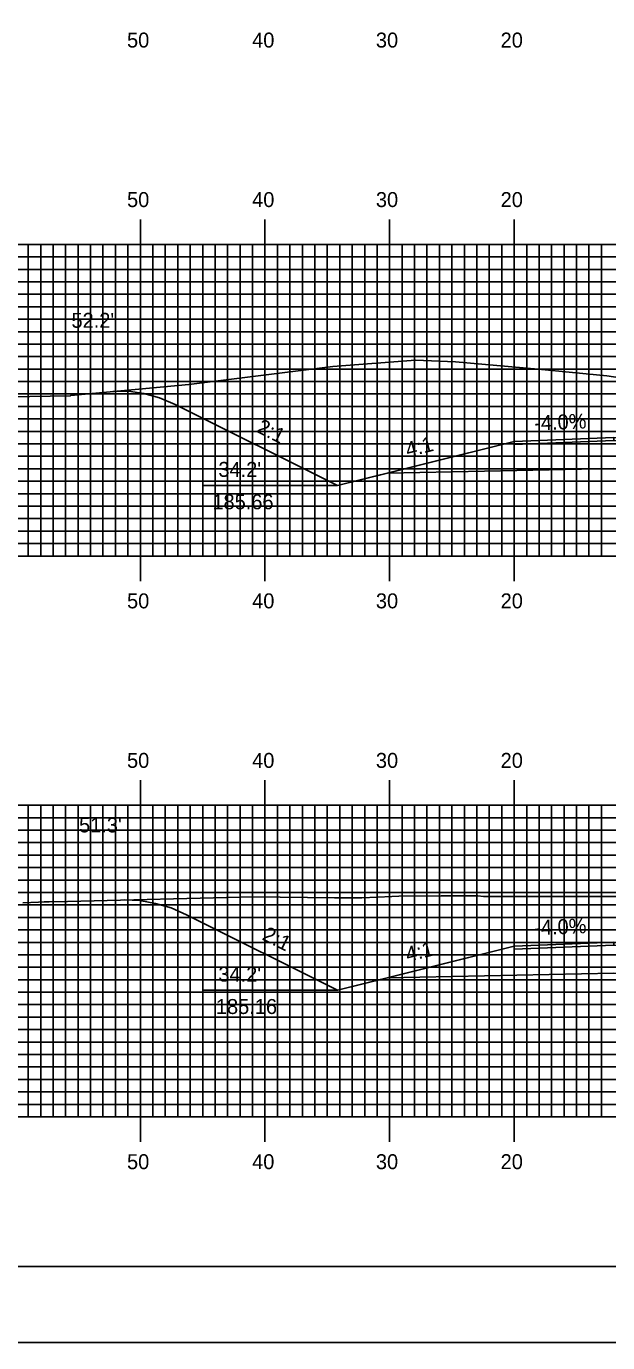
# Model space of a CAD drawing. Extents: x 1798388 to 1798731, y 442591 to 442811.
# Drawn here: x 1798494.3 to 1798541, y 442590.5 to 442696.2 of the extents above; entities that cross this region are included whole.
import ezdxf

# ---------------------------------------------------------------- set-up
doc = ezdxf.new("R2010")
doc.units = 0
for name, color, linetype in [('ANNOTATION', 7, 'Continuous'), ('BORDER', 7, 'Continuous'), ('D_Roadway_Centerline', 7, 'Continuous'), ('D_Roadway_Edge_Shoulder', 7, 'Continuous'), ('D_Roadway_SlopeLines', 7, 'Continuous'), ('D_Roadway_SubGrade', 7, 'Continuous'), ('D_Text_Standard', 7, 'Continuous'), ('H_V ANNOTATION', 7, 'Continuous'), ('MAJOR', 7, 'Continuous'), ('MINOR', 7, 'Continuous'), ('PDRAIN', 7, 'Continuous'), ('PLOT BOUNDARY', 7, 'Continuous'), ('S_Roadway_Centerline', 7, 'Continuous')]:
    doc.layers.add(name, color=color, linetype=linetype)

msp = doc.modelspace()

# ---------------------------------------------------------------- linework, layer by layer
at = {"layer": 'BORDER'}
msp.add_lwpolyline([(1798403.87, 442596.67), (1798723.87, 442596.67), (1798723.87, 442806.67), (1798403.87, 442806.67)], close=True, dxfattribs=at)
at = {"layer": 'D_Roadway_Centerline'}
for points in [[(1798501.26, 442666.86), (1798502.51, 442666.89), (1798503.76, 442666.72), (1798505.01, 442666.37), (1798506.26, 442665.84), (1798519.3, 442659.33), (1798523.3, 442660.33), (1798533.47, 442662.87), (1798541.47, 442663.19), (1798553.47, 442662.95), (1798565.47, 442662.71), (1798573.47, 442662.39), (1798583.64, 442659.85), (1798587.64, 442658.85), (1798594.53, 442662.29), (1798595.78, 442662.83), (1798597.03, 442663.19), (1798598.28, 442663.39), (1798599.53, 442663.41)], [(1798502.18, 442626.07), (1798503.43, 442626.02), (1798504.68, 442625.8), (1798505.93, 442625.43), (1798507.18, 442624.88), (1798519.3, 442618.83), (1798523.3, 442619.83), (1798533.47, 442622.37), (1798541.47, 442622.69), (1798553.47, 442622.45), (1798565.47, 442622.21), (1798573.47, 442621.89), (1798583.64, 442619.35), (1798587.64, 442618.35), (1798593.98, 442621.51), (1798595.23, 442622.06), (1798596.48, 442622.45), (1798597.73, 442622.68), (1798598.98, 442622.75)]]:
    msp.add_lwpolyline(points, dxfattribs=at)
at = {"layer": 'D_Roadway_Edge_Shoulder'}
for points in [[(1798541.47, 442663.19), (1798533.47, 442662.87), (1798533.47, 442662.62), (1798541.47, 442662.94)], [(1798541.47, 442622.69), (1798533.47, 442622.37), (1798533.47, 442622.12), (1798541.47, 442622.44)]]:
    msp.add_lwpolyline(points, close=True, dxfattribs=at)
at = {"layer": 'D_Roadway_SlopeLines'}
for points in [[(1798519.3, 442659.33), (1798506.26, 442665.84), (1798505.01, 442666.37), (1798503.76, 442666.72), (1798502.51, 442666.89), (1798501.26, 442666.86)], [(1798533.47, 442662.87), (1798519.3, 442659.33)], [(1798519.3, 442618.83), (1798507.18, 442624.88), (1798505.93, 442625.43), (1798504.68, 442625.8), (1798503.43, 442626.02), (1798502.18, 442626.07)], [(1798533.47, 442622.37), (1798519.3, 442618.83)]]:
    msp.add_lwpolyline(points, dxfattribs=at)
at = {"layer": 'D_Roadway_SubGrade'}
for points in [[(1798541.47, 442660.69), (1798523.3, 442660.33), (1798533.47, 442662.87), (1798533.47, 442662.62), (1798541.47, 442662.94), (1798553.47, 442662.7), (1798565.47, 442662.46), (1798573.47, 442662.14), (1798573.47, 442662.39), (1798583.64, 442659.85), (1798565.47, 442660.21), (1798553.47, 442660.45)], [(1798541.47, 442620.19), (1798523.3, 442619.83), (1798533.47, 442622.37), (1798533.47, 442622.12), (1798541.47, 442622.44), (1798553.47, 442622.2), (1798565.47, 442621.96), (1798573.47, 442621.64), (1798573.47, 442621.89), (1798583.64, 442619.35), (1798565.47, 442619.71), (1798553.47, 442619.95)]]:
    msp.add_lwpolyline(points, close=True, dxfattribs=at)
at = {"layer": 'MAJOR'}
for p, q in [((1798503.47, 442680.67), (1798503.47, 442678.67)), ((1798513.47, 442680.67), (1798513.47, 442678.67)), ((1798523.47, 442680.67), (1798523.47, 442678.67)), ((1798533.47, 442680.67), (1798533.47, 442678.67)), ((1798413.47, 442678.67), (1798693.47, 442678.67)), ((1798413.47, 442678.67), (1798693.47, 442678.67)), ((1798503.47, 442653.67), (1798503.47, 442678.67)), ((1798513.47, 442653.67), (1798513.47, 442678.67)), ((1798523.47, 442653.67), (1798523.47, 442678.67)), ((1798533.47, 442653.67), (1798533.47, 442678.67)), ((1798413.47, 442673.67), (1798693.47, 442673.67)), ((1798413.47, 442668.67), (1798693.47, 442668.67)), ((1798413.47, 442663.67), (1798693.47, 442663.67)), ((1798413.47, 442658.67), (1798693.47, 442658.67)), ((1798413.47, 442653.67), (1798693.47, 442653.67)), ((1798413.47, 442653.67), (1798693.47, 442653.67)), ((1798503.47, 442651.66), (1798503.47, 442653.67)), ((1798513.47, 442651.66), (1798513.47, 442653.67)), ((1798523.47, 442651.66), (1798523.47, 442653.67)), ((1798533.47, 442651.66), (1798533.47, 442653.67)), ((1798503.47, 442635.67), (1798503.47, 442633.67)), ((1798513.47, 442635.67), (1798513.47, 442633.67)), ((1798523.47, 442635.67), (1798523.47, 442633.67)), ((1798533.47, 442635.67), (1798533.47, 442633.67)), ((1798413.47, 442633.67), (1798693.47, 442633.67)), ((1798413.47, 442633.67), (1798693.47, 442633.67)), ((1798503.47, 442608.67), (1798503.47, 442633.67)), ((1798513.47, 442608.67), (1798513.47, 442633.67)), ((1798523.47, 442608.67), (1798523.47, 442633.67)), ((1798533.47, 442608.67), (1798533.47, 442633.67)), ((1798413.47, 442628.67), (1798693.47, 442628.67)), ((1798413.47, 442623.67), (1798693.47, 442623.67)), ((1798413.47, 442618.67), (1798693.47, 442618.67)), ((1798413.47, 442613.67), (1798693.47, 442613.67)), ((1798413.47, 442608.67), (1798693.47, 442608.67)), ((1798413.47, 442608.67), (1798693.47, 442608.67)), ((1798503.47, 442606.66), (1798503.47, 442608.67)), ((1798513.47, 442606.66), (1798513.47, 442608.67)), ((1798523.47, 442606.66), (1798523.47, 442608.67)), ((1798533.47, 442606.66), (1798533.47, 442608.67))]:
    msp.add_line(p, q, dxfattribs=at)
at = {"layer": 'MINOR'}
for p, q in [((1798494.47, 442653.67), (1798494.47, 442678.67)), ((1798495.47, 442653.67), (1798495.47, 442678.67)), ((1798496.47, 442653.67), (1798496.47, 442678.67)), ((1798497.47, 442653.67), (1798497.47, 442678.67)), ((1798498.47, 442653.67), (1798498.47, 442678.67)), ((1798499.47, 442653.67), (1798499.47, 442678.67)), ((1798500.47, 442653.67), (1798500.47, 442678.67)), ((1798501.47, 442653.67), (1798501.47, 442678.67)), ((1798502.47, 442653.67), (1798502.47, 442678.67)), ((1798504.47, 442653.67), (1798504.47, 442678.67)), ((1798505.47, 442653.67), (1798505.47, 442678.67)), ((1798506.47, 442653.67), (1798506.47, 442678.67)), ((1798507.47, 442653.67), (1798507.47, 442678.67)), ((1798508.47, 442653.67), (1798508.47, 442678.67)), ((1798509.47, 442653.67), (1798509.47, 442678.67)), ((1798510.47, 442653.67), (1798510.47, 442678.67)), ((1798511.47, 442653.67), (1798511.47, 442678.67)), ((1798512.47, 442653.67), (1798512.47, 442678.67)), ((1798514.47, 442653.67), (1798514.47, 442678.67)), ((1798515.47, 442653.67), (1798515.47, 442678.67)), ((1798516.47, 442653.67), (1798516.47, 442678.67)), ((1798517.47, 442653.67), (1798517.47, 442678.67)), ((1798518.47, 442653.67), (1798518.47, 442678.67)), ((1798519.47, 442653.67), (1798519.47, 442678.67)), ((1798520.47, 442653.67), (1798520.47, 442678.67)), ((1798521.47, 442653.67), (1798521.47, 442678.67)), ((1798522.47, 442653.67), (1798522.47, 442678.67)), ((1798524.47, 442653.67), (1798524.47, 442678.67)), ((1798525.47, 442653.67), (1798525.47, 442678.67)), ((1798526.47, 442653.67), (1798526.47, 442678.67)), ((1798527.47, 442653.67), (1798527.47, 442678.67)), ((1798528.47, 442653.67), (1798528.47, 442678.67)), ((1798529.47, 442653.67), (1798529.47, 442678.67)), ((1798530.47, 442653.67), (1798530.47, 442678.67)), ((1798531.47, 442653.67), (1798531.47, 442678.67)), ((1798532.47, 442653.67), (1798532.47, 442678.67)), ((1798534.47, 442653.67), (1798534.47, 442678.67)), ((1798535.47, 442653.67), (1798535.47, 442678.67)), ((1798536.47, 442653.67), (1798536.47, 442678.67)), ((1798537.47, 442653.67), (1798537.47, 442678.67)), ((1798538.47, 442653.67), (1798538.47, 442678.67)), ((1798539.47, 442653.67), (1798539.47, 442678.67)), ((1798540.47, 442653.67), (1798540.47, 442678.67)), ((1798413.47, 442677.67), (1798693.47, 442677.67)), ((1798413.47, 442676.67), (1798693.47, 442676.67)), ((1798413.47, 442675.67), (1798693.47, 442675.67)), ((1798413.47, 442674.67), (1798693.47, 442674.67)), ((1798413.47, 442672.67), (1798693.47, 442672.67)), ((1798413.47, 442671.67), (1798693.47, 442671.67)), ((1798413.47, 442670.67), (1798693.47, 442670.67)), ((1798413.47, 442669.67), (1798693.47, 442669.67)), ((1798413.47, 442667.67), (1798693.47, 442667.67)), ((1798413.47, 442666.67), (1798693.47, 442666.67)), ((1798413.47, 442665.67), (1798693.47, 442665.67)), ((1798413.47, 442664.67), (1798693.47, 442664.67)), ((1798413.47, 442662.67), (1798693.47, 442662.67)), ((1798413.47, 442661.67), (1798693.47, 442661.67)), ((1798413.47, 442660.67), (1798693.47, 442660.67)), ((1798413.47, 442659.67), (1798693.47, 442659.67)), ((1798413.47, 442657.67), (1798693.47, 442657.67)), ((1798413.47, 442656.67), (1798693.47, 442656.67)), ((1798413.47, 442655.67), (1798693.47, 442655.67)), ((1798413.47, 442654.67), (1798693.47, 442654.67)), ((1798494.47, 442608.67), (1798494.47, 442633.67)), ((1798495.47, 442608.67), (1798495.47, 442633.67)), ((1798496.47, 442608.67), (1798496.47, 442633.67)), ((1798497.47, 442608.67), (1798497.47, 442633.67)), ((1798498.47, 442608.67), (1798498.47, 442633.67)), ((1798499.47, 442608.67), (1798499.47, 442633.67)), ((1798500.47, 442608.67), (1798500.47, 442633.67)), ((1798501.47, 442608.67), (1798501.47, 442633.67)), ((1798502.47, 442608.67), (1798502.47, 442633.67)), ((1798504.47, 442608.67), (1798504.47, 442633.67)), ((1798505.47, 442608.67), (1798505.47, 442633.67)), ((1798506.47, 442608.67), (1798506.47, 442633.67)), ((1798507.47, 442608.67), (1798507.47, 442633.67)), ((1798508.47, 442608.67), (1798508.47, 442633.67)), ((1798509.47, 442608.67), (1798509.47, 442633.67)), ((1798510.47, 442608.67), (1798510.47, 442633.67)), ((1798511.47, 442608.67), (1798511.47, 442633.67)), ((1798512.47, 442608.67), (1798512.47, 442633.67)), ((1798514.47, 442608.67), (1798514.47, 442633.67)), ((1798515.47, 442608.67), (1798515.47, 442633.67)), ((1798516.47, 442608.67), (1798516.47, 442633.67)), ((1798517.47, 442608.67), (1798517.47, 442633.67)), ((1798518.47, 442608.67), (1798518.47, 442633.67)), ((1798519.47, 442608.67), (1798519.47, 442633.67)), ((1798520.47, 442608.67), (1798520.47, 442633.67)), ((1798521.47, 442608.67), (1798521.47, 442633.67)), ((1798522.47, 442608.67), (1798522.47, 442633.67)), ((1798524.47, 442608.67), (1798524.47, 442633.67)), ((1798525.47, 442608.67), (1798525.47, 442633.67)), ((1798526.47, 442608.67), (1798526.47, 442633.67)), ((1798527.47, 442608.67), (1798527.47, 442633.67)), ((1798528.47, 442608.67), (1798528.47, 442633.67)), ((1798529.47, 442608.67), (1798529.47, 442633.67)), ((1798530.47, 442608.67), (1798530.47, 442633.67)), ((1798531.47, 442608.67), (1798531.47, 442633.67)), ((1798532.47, 442608.67), (1798532.47, 442633.67)), ((1798534.47, 442608.67), (1798534.47, 442633.67)), ((1798535.47, 442608.67), (1798535.47, 442633.67)), ((1798536.47, 442608.67), (1798536.47, 442633.67)), ((1798537.47, 442608.67), (1798537.47, 442633.67)), ((1798538.47, 442608.67), (1798538.47, 442633.67)), ((1798539.47, 442608.67), (1798539.47, 442633.67)), ((1798540.47, 442608.67), (1798540.47, 442633.67)), ((1798413.47, 442632.67), (1798693.47, 442632.67)), ((1798413.47, 442631.67), (1798693.47, 442631.67)), ((1798413.47, 442630.67), (1798693.47, 442630.67)), ((1798413.47, 442629.67), (1798693.47, 442629.67)), ((1798413.47, 442627.67), (1798693.47, 442627.67)), ((1798413.47, 442626.67), (1798693.47, 442626.67)), ((1798413.47, 442625.67), (1798693.47, 442625.67)), ((1798413.47, 442624.67), (1798693.47, 442624.67)), ((1798413.47, 442622.67), (1798693.47, 442622.67)), ((1798413.47, 442621.67), (1798693.47, 442621.67)), ((1798413.47, 442620.67), (1798693.47, 442620.67)), ((1798413.47, 442619.67), (1798693.47, 442619.67)), ((1798413.47, 442617.67), (1798693.47, 442617.67)), ((1798413.47, 442616.67), (1798693.47, 442616.67)), ((1798413.47, 442615.67), (1798693.47, 442615.67)), ((1798413.47, 442614.67), (1798693.47, 442614.67)), ((1798413.47, 442612.67), (1798693.47, 442612.67)), ((1798413.47, 442611.67), (1798693.47, 442611.67)), ((1798413.47, 442610.67), (1798693.47, 442610.67)), ((1798413.47, 442609.67), (1798693.47, 442609.67))]:
    msp.add_line(p, q, dxfattribs=at)
at = {"layer": 'PDRAIN'}
for p, q in [((1798508.57, 442659.33), (1798519.3, 442659.33)), ((1798508.57, 442618.83), (1798519.3, 442618.83))]:
    msp.add_line(p, q, dxfattribs=at)
at = {"layer": 'PLOT BOUNDARY'}
msp.add_lwpolyline([(1798387.68, 442590.55), (1798727.68, 442590.55), (1798727.68, 442810.55), (1798387.68, 442810.55)], close=True, dxfattribs=at)
at = {"layer": 'S_Roadway_Centerline'}
for points in [[(1798492.98, 442666.44), (1798497.86, 442666.51), (1798497.88, 442666.56), (1798507.35, 442667.42), (1798518.91, 442668.88), (1798525.56, 442669.39), (1798528.75, 442669.26), (1798535.39, 442668.65), (1798540.9, 442668.12), (1798555.11, 442666.02), (1798559.56, 442665.78), (1798563.02, 442665.3), (1798577.82, 442664.54), (1798581.28, 442664.51), (1798584.09, 442664.22), (1798602.09, 442663.27)], [(1798494.03, 442625.84), (1798495.29, 442625.9), (1798495.76, 442625.92), (1798496.16, 442625.93), (1798497.61, 442625.96), (1798512.51, 442626.32), (1798519.04, 442626.25), (1798521.23, 442626.25), (1798522.5, 442626.3), (1798523.66, 442626.34), (1798524.2, 442626.37), (1798527.61, 442626.4), (1798530.56, 442626.41), (1798531, 442626.34), (1798542.97, 442626.36), (1798551.12, 442626.28), (1798565.19, 442626.16), (1798565.66, 442626.14), (1798567.1, 442625.92), (1798572.88, 442624.87), (1798584.14, 442623.68), (1798589.61, 442623.12), (1798596.58, 442622.76), (1798602.18, 442622.75)]]:
    msp.add_lwpolyline(points, dxfattribs=at)

# ---------------------------------------------------------------- texts
at = {"layer": 'ANNOTATION'}
for s, rotation, p in [('-4.0%', 2.2906, (1798535.1, 442663.74)), ('2:1', 333.4349, (1798512.71, 442663.65)), ('4:1', 14.0362, (1798524.92, 442661.59)), ('2:1', 333.4349, (1798513.17, 442622.92)), ('-4.0%', 2.2906, (1798535.1, 442623.24)), ('4:1', 14.0362, (1798524.92, 442621.09))]:
    msp.add_text(s, height=1.2, rotation=rotation, dxfattribs=at).set_placement(p)
for s, p in [("34.2'", (1798509.73, 442660.02)), ('185.66', (1798509.25, 442657.42)), ("34.2'", (1798509.73, 442619.52)), ('185.16', (1798509.53, 442616.92))]:
    msp.add_text(s, height=1.2, dxfattribs=at).set_placement(p)
at = {"layer": 'D_Text_Standard'}
for s, p in [("52.2'", (1798497.94, 442671.98)), ("51.3'", (1798498.55, 442631.49))]:
    msp.add_text(s, height=1.2, dxfattribs=at).set_placement(p)
at = {"layer": 'H_V ANNOTATION'}
for s, p in [('50', (1798502.4, 442694.47)), ('40', (1798512.44, 442694.47)), ('30', (1798522.37, 442694.47)), ('20', (1798532.38, 442694.47)), ('50', (1798502.4, 442681.67)), ('40', (1798512.44, 442681.67)), ('30', (1798522.37, 442681.67)), ('20', (1798532.38, 442681.67)), ('50', (1798502.4, 442649.47)), ('40', (1798512.44, 442649.47)), ('30', (1798522.37, 442649.47)), ('20', (1798532.38, 442649.47)), ('50', (1798502.4, 442636.67)), ('40', (1798512.44, 442636.67)), ('30', (1798522.37, 442636.67)), ('20', (1798532.38, 442636.67)), ('50', (1798502.4, 442604.47)), ('40', (1798512.44, 442604.47)), ('30', (1798522.37, 442604.47)), ('20', (1798532.38, 442604.47))]:
    msp.add_text(s, height=1.2, dxfattribs=at).set_placement(p)

doc.saveas('drawing.dxf')
